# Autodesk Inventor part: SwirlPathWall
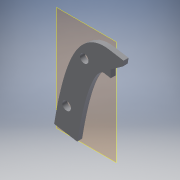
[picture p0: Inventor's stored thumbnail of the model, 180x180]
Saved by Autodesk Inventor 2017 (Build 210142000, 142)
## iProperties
Created: 2017-05
Part Number: SwirlPathWall
Material: Generic
Document SubType Name: Modeling
Designer: 1460374
Density: 1 g/cm^3
Appearance: Default
Author: 1460374
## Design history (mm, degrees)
workplane "Work Plane1"
sketch "Sketch1" dims "d0" = 17.78
  geometry: L1 (17.426, 20.735)-(20.317, 38.278); L2 (-3.526, -34.773)-(-21.069, -31.882); C1 r 3.175 at (1.862, 22.806) reference; C2 r 3.175 at (-11.526, -15.179) reference; 2 further points
  constraints: 4 end point, 1 perpendicular, 4 other
extrude "Extrusion1" new body sketch "Sketch1" distance "d1" = 3.81; taper "d2" = 0 deg
sketch "Sketch2"
  geometry: L1 (0, -17.78)-(0, 0) reference; L2 (3.81, -17.844)-(0, -17.844); L3 (0, -17.844)-(0, 0); L4 (0, 0)-(3.81, 0); L5 (3.81, 0)-(3.81, -17.844); 1 further point
  constraints: 8 end point, 2 parallel, 1 horizontal, 1 perpendicular
extrude "Extrusion2" join sketch "Sketch2" distance "d3" = 11.7475; taper "d4" = 0 deg
sketch "Sketch3"
  geometry: L1 (33.805, 34.028)-(22.142, 25.665) reference; L2 (22.142, 25.665)-(22.142, 19.892); L3 (17.415, 20.672)-(29.006, 18.761) reference; L4 (31.908, 36.368)-(29.006, 18.761) reference; L5 (31.217, 32.172)-(29.006, 18.761); L6 (29.006, 18.761)-(22.142, 19.892); L7 (31.217, 32.172)-(22.142, 25.665); A1 r 6.35 centre (20.5, 19.531) between (22.142, 25.665) and (19.405, 25.786) reference; 1 further point
  constraints: 8 end point, 3 point on line, 2 collinear, 1 perpendicular, 1 vertical
extrude "Extrusion3" cut sketch "Sketch3" distance "d5" = 3.81; taper "d6" = 0 deg
sketch "Sketch4"
  geometry: L1 (22.142, 19.892)-(22.142, 25.665) reference; L2 (22.142, 25.665)-(31.217, 32.172) reference; L3 (31.908, 36.368)-(31.217, 32.172) reference; L4 (20.317, 38.278)-(31.908, 36.368) reference; L5 (-21.069, -31.882)-(-3.526, -34.773) reference; L6 (17.415, 20.672)-(17.426, 20.735) reference; L7 (17.415, 20.672)-(22.142, 19.892) reference; C1 r 3.175 at (1.862, 22.806) reference; C2 r 3.175 at (-11.526, -15.179) reference; C3 r 3.175 at (-11.526, -15.179) reference; C4 r 3.275 at (1.862, 22.806); C5 r 3.275 at (-11.526, -15.179); 1 further point
  constraints: 2 centre point, 2 other
  dimensions: "d7" = 0.1 radial gap between concentric circles of C1 C4; "d8" = 0.1 radial gap between concentric circles of C2 C5
  node "Projected Loop1"
workplane "Work Plane2"
extrude "Extrusion4" cut sketch "Sketch4" stored distance "d9" = 10.4775; taper "d10" = 0 deg
body "Solid1"
node "Reference1"
node "Reference2"
node "Reference3"
node "Reference4"
node "Reference5"
